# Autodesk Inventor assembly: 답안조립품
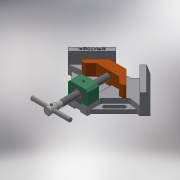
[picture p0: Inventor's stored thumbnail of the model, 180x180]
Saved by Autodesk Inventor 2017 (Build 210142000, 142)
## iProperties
Part Number: 답안조립품
Material: 일반
Document SubType Name: Assembly
Designer: 222
Author: 222
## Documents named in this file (11)
- C:\Users\222\Desktop\700506V1013\답안조립품.iam
- C:\Users\222\Desktop\700506V1013\베이스.ipt
- C:\Users\222\Desktop\700506V1013\리드스크류.ipt
- C:\Users\222\Desktop\700506V1013\멈춤나사 M4x5.ipt
- C:\Users\222\Desktop\700506V1013\멈춤나사 M4x10.ipt
- C:\Users\222\Desktop\700506V1013\볼트 M4x16.ipt
- C:\Users\222\Desktop\700506V1013\부시.ipt
- C:\Users\222\Desktop\700506V1013\서포트.ipt
- C:\Users\222\Desktop\700506V1013\조.ipt
- C:\Users\222\Desktop\700506V1013\평행 핀 2.5x24.ipt
- C:\Users\222\Desktop\700506V1013\핸들.ipt
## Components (1 placed, 1 different names)
1. 핸들:1
